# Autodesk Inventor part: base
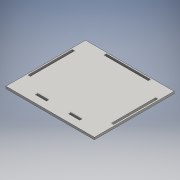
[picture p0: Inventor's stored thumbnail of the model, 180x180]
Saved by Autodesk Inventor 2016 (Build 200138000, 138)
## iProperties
Created: 2016-06
Part Number: base
Material: Genérico
Document SubType Name: Modeling
Designer: adm
Density: 1 g/cm^3
Appearance: Valor por defecto
Author: adm
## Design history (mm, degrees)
sketch "Boceto1"
  geometry: L1 (-60, -50)-(60, -50); L2 (60, -50)-(60, 50); L3 (60, 50)-(-60, 50); L4 (-60, 50)-(-60, -50); L5 (-60, -50)-(60, 50); L6 (60, -50)-(-60, 50); L7 (58, 30)-(58, -30); L8 (-58, -30)-(-58, 30); L9 (-55, 30)-(-55, -30); L10 (55, -30)-(55, 30); L11 (-58, -30)-(-55, -30); L12 (55, -30)-(58, -30); L13 (-58, 30)-(-55, 30); L14 (-30, 48)-(-30, 45); L15 (30, 45)-(-30, 45); L16 (-30, 48)-(30, 48); L17 (55, 30)-(58, 30); L18 (30, 48)-(30, 45); L19 (30, -45)-(30, -48); L20 (-30, -45)-(-30, -48); L21 (30, -48)-(-30, -48); L22 (-30, -45)-(30, -45); 1 further point
  constraints: 44 end point, 6 parallel, 3 perpendicular, 2 midpoint, 1 horizontal
  dimensions: "d0" = 100 distance of L2.end L1.end; "d1" = 120 distance of L2.end L3.end; "d12" = 60 distance between parallel lines of L19 L20
extrude "Extrusión1" new body sketch "Boceto1" distance "d8" = 3; taper "d9" = 0 deg
sketch "Boceto2"
  geometry: L1 (30, -45)-(-30, -45) reference; L2 (30, -48)-(-30, -48) reference; L3 (-15, -45)-(-15, -48); L4 (15, -45)-(15, -48); L5 (-15, -45)-(15, -45); L6 (-15, -48)-(15, -48); L7 (-60, -50)-(60, -50) reference; 1 further point
  constraints: 8 end point, 1 collinear, 1 parallel
extrude "Extrusión2" join sketch "Boceto2" distance "d15" = 3; taper "d16" = 0 deg
sketch "Boceto3"
  geometry: L1 (120, 0)-(120, 3) reference; L2 (0, 0)-(120, 0); L3 (120, 0)-(120, 3); L4 (120, 3)-(0, 3); L5 (0, 3)-(0, 0); 1 further point
  constraints: 8 end point, 2 parallel, 1 horizontal, 1 perpendicular
extrude "Extrusión3" join sketch "Boceto3" distance "d17" = 8; taper "d18" = 0 deg
node "Sólido1"
other parameters: "d2" = 2, "d3" = 3
